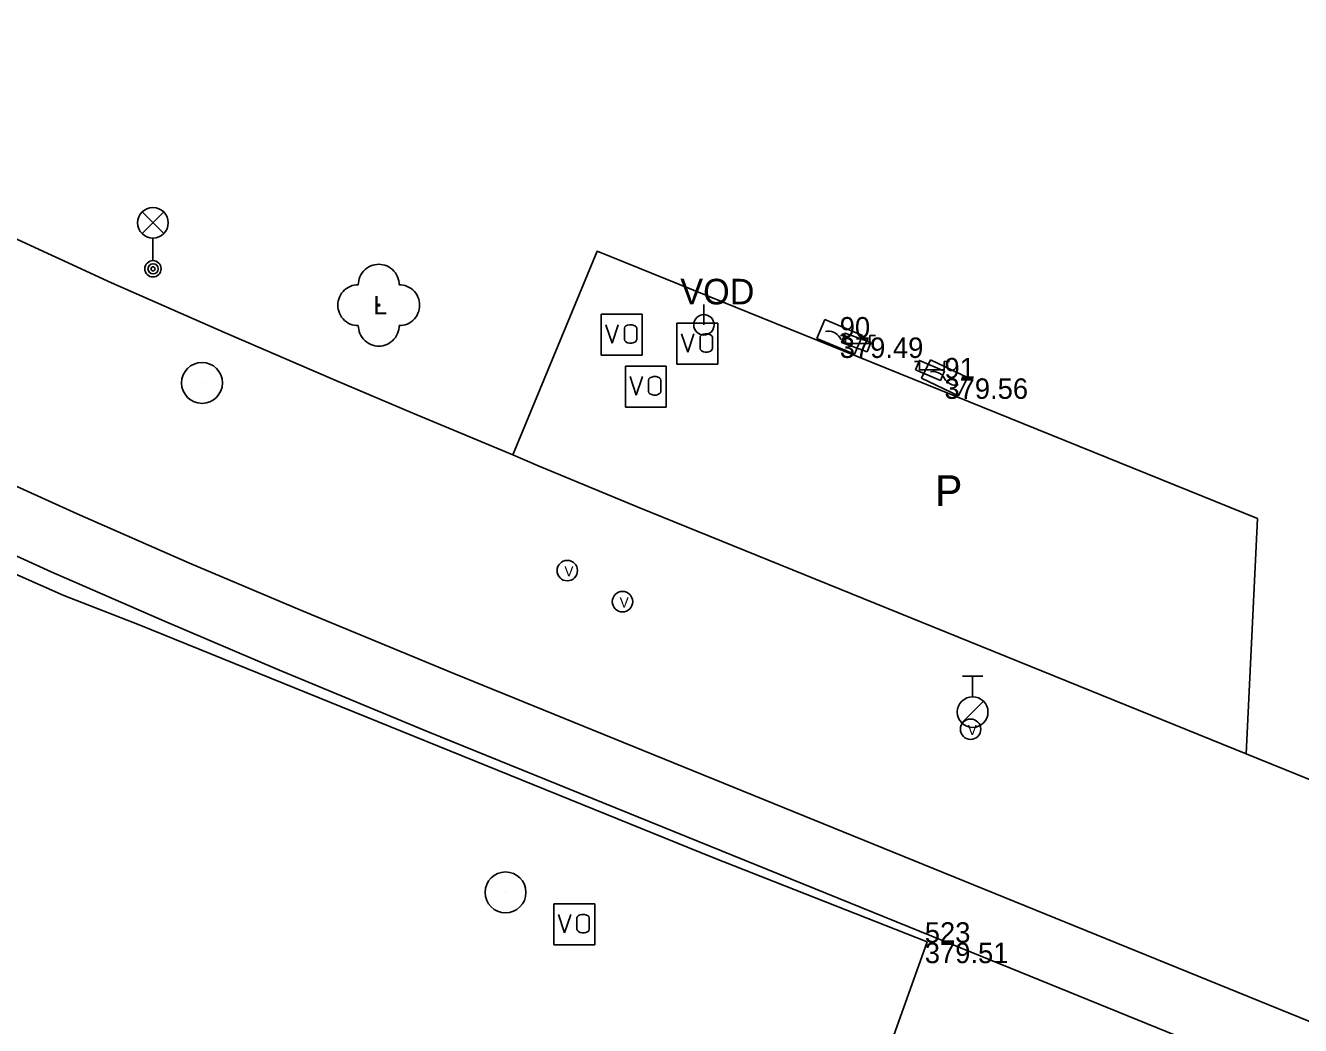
# Model space of a CAD drawing. Extents: x -836568 to -836015, y -1070547 to -1070212.
# Drawn here: x -836391.76 to -836360.58, y -1070409.55 to -1070385.1 of the extents above; entities that cross this region are included whole.
import ezdxf

# ---------------------------------------------------------------- set-up
doc = ezdxf.new("R2010")
doc.units = 0
for name, color, linetype in [('BodPole_mer', 7, 'Continuous'), ('BodPole_popis', 7, 'Continuous'), ('Doprava_hranice', 7, 'Continuous'), ('Doprava_kody', 7, 'Continuous'), ('PovrZnIS_body', 7, 'Continuous'), ('PovrZnIS_hranice', 7, 'Continuous'), ('PovrZnIS_kody', 7, 'Continuous'), ('Stavby_linie', 7, 'Continuous'), ('Zelen_body', 7, 'Continuous')]:
    doc.layers.add(name, color=color, linetype=linetype)

msp = doc.modelspace()

# ---------------------------------------------------------------- linework, layer by layer
at = {"layer": 'BodPole_mer'}
for p, q in [((-836377.78, -1070390.62), (-836377.78, -1070390.62)), ((-836388.64, -1070391.05), (-836388.64, -1070391.05)), ((-836389.65, -1070391.39), (-836389.65, -1070391.39)), ((-836383.12, -1070391.94), (-836383.12, -1070391.94)), ((-836375.17, -1070392.42), (-836375.17, -1070392.42)), ((-836386.89, -1070392.61), (-836386.89, -1070392.61)), ((-836377.18, -1070392.66), (-836377.18, -1070392.66)), ((-836375.33, -1070392.88), (-836375.33, -1070392.88)), ((-836371.85, -1070392.73), (-836371.85, -1070392.73)), ((-836371.81, -1070392.85), (-836371.81, -1070392.85)), ((-836371.81, -1070392.85), (-836371.81, -1070392.85)), ((-836371.72, -1070392.62), (-836371.72, -1070392.62)), ((-836371.72, -1070392.62), (-836371.72, -1070392.62)), ((-836371.09, -1070392.85), (-836371.09, -1070392.85)), ((-836371.09, -1070392.85), (-836371.09, -1070392.85)), ((-836371.18, -1070393.08), (-836371.18, -1070393.08)), ((-836371.18, -1070393.08), (-836371.18, -1070393.08)), ((-836370, -1070393.52), (-836370, -1070393.52)), ((-836370, -1070393.52), (-836370, -1070393.52)), ((-836369.9, -1070393.29), (-836369.9, -1070393.29)), ((-836369.9, -1070393.29), (-836369.9, -1070393.29)), ((-836384.17, -1070393.78), (-836384.17, -1070393.78)), ((-836369.39, -1070393.78), (-836369.39, -1070393.78)), ((-836369.39, -1070393.78), (-836369.39, -1070393.78)), ((-836369.29, -1070393.55), (-836369.29, -1070393.55)), ((-836369.29, -1070393.55), (-836369.29, -1070393.55)), ((-836369.29, -1070393.73), (-836369.29, -1070393.73)), ((-836387.44, -1070393.84), (-836387.44, -1070393.84)), ((-836376.59, -1070393.93), (-836376.59, -1070393.93)), ((-836382.29, -1070394.58), (-836382.29, -1070394.58)), ((-836379.84, -1070395.6), (-836379.84, -1070395.6)), ((-836379.24, -1070395.86), (-836379.24, -1070395.86)), ((-836376.76, -1070396.89), (-836376.76, -1070396.89)), ((-836390.49, -1070397.04), (-836390.49, -1070397.04)), ((-836361.64, -1070397.16), (-836361.64, -1070397.16)), ((-836391.13, -1070398.46), (-836391.13, -1070398.46)), ((-836387.75, -1070398.25), (-836387.75, -1070398.25)), ((-836378.51, -1070398.43), (-836378.51, -1070398.43)), ((-836390.82, -1070399.04), (-836390.82, -1070399.04)), ((-836385.01, -1070399.41), (-836385.01, -1070399.41)), ((-836377.16, -1070399.19), (-836377.16, -1070399.19)), ((-836388.98, -1070399.76), (-836388.98, -1070399.76)), ((-836388.36, -1070399.67), (-836388.36, -1070399.67)), ((-836369.55, -1070399.81), (-836369.55, -1070399.81)), ((-836385.59, -1070400.85), (-836385.59, -1070400.85)), ((-836381.28, -1070400.95), (-836381.28, -1070400.95)), ((-836368.6, -1070401.89), (-836368.6, -1070401.89)), ((-836381.91, -1070402.37), (-836381.91, -1070402.37)), ((-836368.65, -1070402.31), (-836368.65, -1070402.31)), ((-836361.91, -1070402.91), (-836361.91, -1070402.91)), ((-836374.95, -1070405.45), (-836374.95, -1070405.45)), ((-836369.06, -1070405.92), (-836369.06, -1070405.92)), ((-836380.02, -1070406.3), (-836380.02, -1070406.3)), ((-836378.34, -1070407.08), (-836378.34, -1070407.08)), ((-836369.77, -1070407.53), (-836369.77, -1070407.53)), ((-836369.71, -1070407.51), (-836369.71, -1070407.51)), ((-836369.6, -1070407.37), (-836369.6, -1070407.37))]:
    msp.add_line(p, q, dxfattribs=at)
at = {"layer": 'Doprava_hranice'}
for points in [[(-836354.29, -1070413.6), (-836369.6, -1070407.37), (-836381.91, -1070402.37), (-836385.59, -1070400.85), (-836388.36, -1070399.67), (-836391.13, -1070398.46), (-836393.85, -1070397.22), (-836395.73, -1070396.35), (-836398.41, -1070395.08), (-836401.16, -1070393.77), (-836403.85, -1070392.4), (-836406.54, -1070391.05), (-836409.24, -1070389.65), (-836411.89, -1070388.24), (-836414.55, -1070386.78), (-836417.54, -1070385.1), (-836418.59, -1070387.07)], [(-836396.93, -1070387.99), (-836395.12, -1070388.87), (-836392.38, -1070390.14), (-836389.65, -1070391.39), (-836386.89, -1070392.61), (-836384.17, -1070393.78), (-836382.29, -1070394.58), (-836379.84, -1070395.6), (-836379.24, -1070395.86), (-836376.76, -1070396.89), (-836369.55, -1070399.81), (-836361.91, -1070402.91), (-836351.68, -1070407.06)], [(-836379.84, -1070395.6), (-836377.78, -1070390.62), (-836361.64, -1070397.16), (-836361.91, -1070402.91)], [(-836294.78, -1070436.14), (-836298.75, -1070434.54), (-836300.99, -1070433.61), (-836301.95, -1070433.21), (-836302.68, -1070432.9), (-836308.94, -1070430.38), (-836313.57, -1070428.51), (-836318.21, -1070426.63), (-836324.7, -1070423.98), (-836329.32, -1070422.08), (-836333.96, -1070420.19), (-836342.84, -1070416.58), (-836353.67, -1070412.18), (-836369.06, -1070405.92), (-836381.28, -1070400.95), (-836385.01, -1070399.41), (-836387.75, -1070398.25), (-836390.49, -1070397.04), (-836393.21, -1070395.81), (-836395.03, -1070394.97), (-836397.75, -1070393.68), (-836399.24, -1070392.97)]]:
    msp.add_lwpolyline(points, dxfattribs=at)
at = {"layer": 'PovrZnIS_body'}
for p, q in [((-836388.905, -1070390.19), (-836388.375, -1070389.66)), ((-836388.905, -1070389.66), (-836388.375, -1070390.19)), ((-836388.64, -1070390.85), (-836388.64, -1070390.3)), ((-836375.17, -1070392.42), (-836375.17, -1070391.92)), ((-836376.68, -1070392.16), (-836377.68, -1070392.16)), ((-836377.68, -1070392.16), (-836377.68, -1070393.16)), ((-836376.68, -1070393.16), (-836376.68, -1070392.16)), ((-836374.83, -1070392.38), (-836375.83, -1070392.38)), ((-836375.83, -1070392.38), (-836375.83, -1070393.38)), ((-836374.83, -1070393.38), (-836374.83, -1070392.38)), ((-836372.408, -1070392.754), (-836372.214, -1070392.293)), ((-836372.214, -1070392.293), (-836371.292, -1070392.68)), ((-836371.486, -1070393.141), (-836372.408, -1070392.754)), ((-836371.292, -1070392.68), (-836371.486, -1070393.141)), ((-836377.68, -1070393.16), (-836376.68, -1070393.16)), ((-836376.09, -1070393.43), (-836377.09, -1070393.43)), ((-836377.09, -1070393.43), (-836377.09, -1070394.43)), ((-836376.09, -1070394.43), (-836376.09, -1070393.43)), ((-836375.83, -1070393.38), (-836374.83, -1070393.38)), ((-836369.848, -1070393.728), (-836369.633, -1070393.277)), ((-836369.633, -1070393.277), (-836368.73, -1070393.706)), ((-836368.945, -1070394.158), (-836369.848, -1070393.728)), ((-836368.73, -1070393.706), (-836368.945, -1070394.158)), ((-836377.09, -1070394.43), (-836376.09, -1070394.43)), ((-836368.85, -1070401.015), (-836368.35, -1070401.015)), ((-836368.6, -1070401.015), (-836368.6, -1070401.515)), ((-836368.335, -1070401.625), (-836368.865, -1070402.155)), ((-836377.84, -1070406.58), (-836378.84, -1070406.58)), ((-836378.84, -1070406.58), (-836378.84, -1070407.58)), ((-836377.84, -1070407.58), (-836377.84, -1070406.58)), ((-836378.84, -1070407.58), (-836377.84, -1070407.58))]:
    msp.add_line(p, q, dxfattribs=at)
for points in [[(-836377.565, -1070392.417), (-836377.415, -1070392.867)], [(-836377.415, -1070392.867), (-836377.265, -1070392.417)], [(-836377.113, -1070392.501), (-836377.103, -1070392.471), (-836377.08, -1070392.448), (-836377.034, -1070392.427), (-836376.989, -1070392.417), (-836376.929, -1070392.417), (-836376.9, -1070392.425), (-836376.843, -1070392.45), (-836376.823, -1070392.471), (-836376.813, -1070392.501)], [(-836377.113, -1070392.782), (-836377.113, -1070392.501)], [(-836376.813, -1070392.782), (-836376.813, -1070392.501)], [(-836372.197, -1070392.584), (-836372.15, -1070392.576), (-836372.1, -1070392.576), (-836372.049, -1070392.583), (-836371.999, -1070392.599), (-836371.953, -1070392.623), (-836371.912, -1070392.654), (-836371.878, -1070392.691), (-836371.85, -1070392.73)], [(-836377.113, -1070392.782), (-836377.103, -1070392.813), (-836377.08, -1070392.835), (-836377.034, -1070392.857), (-836376.989, -1070392.867), (-836376.929, -1070392.867), (-836376.9, -1070392.859), (-836376.843, -1070392.833), (-836376.823, -1070392.813), (-836376.813, -1070392.782)], [(-836375.715, -1070392.637), (-836375.565, -1070393.087)], [(-836375.565, -1070393.087), (-836375.415, -1070392.637)], [(-836375.263, -1070392.721), (-836375.253, -1070392.691), (-836375.23, -1070392.668), (-836375.184, -1070392.647), (-836375.139, -1070392.637), (-836375.079, -1070392.637), (-836375.05, -1070392.645), (-836374.993, -1070392.67), (-836374.973, -1070392.691), (-836374.963, -1070392.721)], [(-836375.263, -1070393.002), (-836375.263, -1070392.721)], [(-836374.963, -1070393.002), (-836374.963, -1070392.721)], [(-836371.85, -1070392.73), (-836371.823, -1070392.769), (-836371.788, -1070392.805), (-836371.747, -1070392.836), (-836371.701, -1070392.86), (-836371.652, -1070392.876), (-836371.601, -1070392.884), (-836371.551, -1070392.883), (-836371.504, -1070392.875)], [(-836375.263, -1070393.002), (-836375.253, -1070393.033), (-836375.23, -1070393.055), (-836375.184, -1070393.077), (-836375.139, -1070393.087), (-836375.079, -1070393.087), (-836375.05, -1070393.079), (-836374.993, -1070393.053), (-836374.973, -1070393.033), (-836374.963, -1070393.002)], [(-836376.975, -1070393.687), (-836376.825, -1070394.137)], [(-836376.825, -1070394.137), (-836376.675, -1070393.687)], [(-836376.523, -1070393.771), (-836376.513, -1070393.741), (-836376.49, -1070393.718), (-836376.444, -1070393.697), (-836376.399, -1070393.687), (-836376.339, -1070393.687), (-836376.31, -1070393.695), (-836376.253, -1070393.72), (-836376.233, -1070393.741), (-836376.223, -1070393.771)], [(-836376.523, -1070394.052), (-836376.523, -1070393.771)], [(-836376.223, -1070394.052), (-836376.223, -1070393.771)], [(-836369.63, -1070393.568), (-836369.582, -1070393.562), (-836369.532, -1070393.564), (-836369.482, -1070393.574), (-836369.433, -1070393.593), (-836369.388, -1070393.619), (-836369.349, -1070393.652), (-836369.316, -1070393.689), (-836369.29, -1070393.73)], [(-836369.29, -1070393.73), (-836369.265, -1070393.771), (-836369.232, -1070393.808), (-836369.192, -1070393.841), (-836369.148, -1070393.867), (-836369.099, -1070393.885), (-836369.049, -1070393.895), (-836368.999, -1070393.897), (-836368.951, -1070393.891)], [(-836376.523, -1070394.052), (-836376.513, -1070394.083), (-836376.49, -1070394.105), (-836376.444, -1070394.127), (-836376.399, -1070394.137), (-836376.339, -1070394.137), (-836376.31, -1070394.129), (-836376.253, -1070394.103), (-836376.233, -1070394.083), (-836376.223, -1070394.052)], [(-836378.725, -1070406.837), (-836378.575, -1070407.287)], [(-836378.575, -1070407.287), (-836378.425, -1070406.837)], [(-836378.273, -1070406.921), (-836378.263, -1070406.891), (-836378.24, -1070406.868), (-836378.194, -1070406.847), (-836378.149, -1070406.837), (-836378.089, -1070406.837), (-836378.06, -1070406.845), (-836378.003, -1070406.87), (-836377.983, -1070406.891), (-836377.973, -1070406.921)], [(-836378.273, -1070407.202), (-836378.273, -1070406.921)], [(-836377.973, -1070407.202), (-836377.973, -1070406.921)], [(-836378.273, -1070407.202), (-836378.263, -1070407.233), (-836378.24, -1070407.255), (-836378.194, -1070407.277), (-836378.149, -1070407.287), (-836378.089, -1070407.287), (-836378.06, -1070407.279), (-836378.003, -1070407.253), (-836377.983, -1070407.233), (-836377.973, -1070407.202)]]:
    msp.add_lwpolyline(points, dxfattribs=at)
for centre, radius in [((-836375.17, -1070392.42), 0.25), ((-836387.44, -1070393.84), 0.5), ((-836378.51, -1070398.43), 0.25), ((-836377.16, -1070399.19), 0.25), ((-836368.6, -1070401.89), 0.375), ((-836368.65, -1070402.31), 0.25), ((-836380.02, -1070406.3), 0.5)]:
    msp.add_circle(centre, radius, dxfattribs=at)
for centre, major_axis in [((-836388.64, -1070389.925), (0.375, 0)), ((-836388.64, -1070391.05), (0.2, 0)), ((-836388.636, -1070391.05), (0.125, 0)), ((-836388.636, -1070391.05), (0.05, 0))]:
    msp.add_ellipse(centre, major_axis=major_axis, ratio=0.999998, dxfattribs=at)
at = {"layer": 'PovrZnIS_hranice'}
for p, q in [((-836371.81, -1070392.85), (-836371.18, -1070393.08)), ((-836371.81, -1070392.85), (-836371.18, -1070393.08)), ((-836370, -1070393.52), (-836369.39, -1070393.78)), ((-836370, -1070393.52), (-836369.39, -1070393.78))]:
    msp.add_line(p, q, dxfattribs=at)
for points in [[(-836371.81, -1070392.85), (-836371.72, -1070392.62), (-836371.09, -1070392.85), (-836371.18, -1070393.08)], [(-836371.81, -1070392.85), (-836371.72, -1070392.62), (-836371.09, -1070392.85), (-836371.18, -1070393.08)], [(-836370, -1070393.52), (-836369.9, -1070393.29), (-836369.29, -1070393.55), (-836369.39, -1070393.78)], [(-836370, -1070393.52), (-836369.9, -1070393.29), (-836369.29, -1070393.55), (-836369.39, -1070393.78)]]:
    msp.add_lwpolyline(points, dxfattribs=at)
at = {"layer": 'PovrZnIS_kody'}
for p, q in [((-836371.831, -1070392.68), (-836371.71, -1070392.68)), ((-836371.831, -1070392.68), (-836371.71, -1070392.68)), ((-836371.71, -1070392.68), (-836371.71, -1070392.88)), ((-836371.71, -1070392.68), (-836371.71, -1070392.88)), ((-836371.71, -1070392.88), (-836371.11, -1070392.88)), ((-836371.71, -1070392.88), (-836371.11, -1070392.88)), ((-836371.11, -1070392.88), (-836371.11, -1070392.68)), ((-836371.11, -1070392.68), (-836370.976, -1070392.68)), ((-836371.11, -1070392.88), (-836371.11, -1070392.68)), ((-836371.11, -1070392.68), (-836370.976, -1070392.68)), ((-836370.021, -1070393.32), (-836369.9, -1070393.32)), ((-836370.021, -1070393.32), (-836369.9, -1070393.32)), ((-836369.9, -1070393.32), (-836369.9, -1070393.52)), ((-836369.9, -1070393.32), (-836369.9, -1070393.52)), ((-836369.9, -1070393.52), (-836369.3, -1070393.52)), ((-836369.9, -1070393.52), (-836369.3, -1070393.52)), ((-836369.3, -1070393.52), (-836369.3, -1070393.32)), ((-836369.3, -1070393.32), (-836369.166, -1070393.32)), ((-836369.3, -1070393.52), (-836369.3, -1070393.32)), ((-836369.3, -1070393.32), (-836369.166, -1070393.32))]:
    msp.add_line(p, q, dxfattribs=at)
at = {"layer": 'Stavby_linie'}
msp.add_line((-836393.4, -1070397.9), (-836390.82, -1070399.04), dxfattribs=at)
for points in [[(-836369.71, -1070407.51), (-836374.95, -1070405.45), (-836388.98, -1070399.76), (-836390.82, -1070399.04)], [(-836407.72, -1070434.26), (-836402.65, -1070436.98), (-836392.21, -1070442.72), (-836384.11, -1070447.06), (-836383.25, -1070443.91), (-836379.69, -1070432.5), (-836376.35, -1070424), (-836370.7, -1070410.27), (-836369.71, -1070407.51)]]:
    msp.add_lwpolyline(points, dxfattribs=at)
at = {"layer": 'Zelen_body'}
msp.add_line((-836383.12, -1070391.94), (-836383.12, -1070391.94), dxfattribs=at)
for points in [[(-836383.62, -1070391.44), (-836383.618, -1070391.392), (-836383.61, -1070391.343), (-836383.598, -1070391.293), (-836383.58, -1070391.244), (-836383.556, -1070391.195), (-836383.527, -1070391.149), (-836383.493, -1070391.106), (-836383.454, -1070391.067), (-836383.411, -1070391.033), (-836383.365, -1070391.004), (-836383.316, -1070390.98), (-836383.267, -1070390.962), (-836383.217, -1070390.95), (-836383.168, -1070390.942), (-836383.12, -1070390.94), (-836383.072, -1070390.942), (-836383.023, -1070390.95), (-836382.973, -1070390.962), (-836382.924, -1070390.98), (-836382.875, -1070391.004), (-836382.829, -1070391.033), (-836382.786, -1070391.067), (-836382.747, -1070391.106), (-836382.713, -1070391.149), (-836382.684, -1070391.195), (-836382.66, -1070391.244), (-836382.642, -1070391.293), (-836382.63, -1070391.343), (-836382.622, -1070391.392), (-836382.62, -1070391.44)], [(-836383.62, -1070392.44), (-836383.668, -1070392.438), (-836383.717, -1070392.43), (-836383.767, -1070392.418), (-836383.816, -1070392.4), (-836383.865, -1070392.376), (-836383.911, -1070392.347), (-836383.954, -1070392.313), (-836383.993, -1070392.274), (-836384.027, -1070392.231), (-836384.056, -1070392.185), (-836384.08, -1070392.136), (-836384.098, -1070392.087), (-836384.11, -1070392.037), (-836384.118, -1070391.988), (-836384.12, -1070391.94), (-836384.118, -1070391.892), (-836384.11, -1070391.843), (-836384.098, -1070391.793), (-836384.08, -1070391.744), (-836384.056, -1070391.695), (-836384.027, -1070391.649), (-836383.993, -1070391.606), (-836383.954, -1070391.567), (-836383.911, -1070391.533), (-836383.865, -1070391.504), (-836383.816, -1070391.48), (-836383.767, -1070391.462), (-836383.717, -1070391.45), (-836383.668, -1070391.442), (-836383.62, -1070391.44)], [(-836382.62, -1070391.44), (-836382.572, -1070391.442), (-836382.523, -1070391.45), (-836382.473, -1070391.462), (-836382.424, -1070391.48), (-836382.375, -1070391.504), (-836382.329, -1070391.533), (-836382.286, -1070391.567), (-836382.247, -1070391.606), (-836382.213, -1070391.649), (-836382.184, -1070391.695), (-836382.16, -1070391.744), (-836382.142, -1070391.793), (-836382.13, -1070391.843), (-836382.122, -1070391.892), (-836382.12, -1070391.94), (-836382.122, -1070391.988), (-836382.13, -1070392.037), (-836382.142, -1070392.087), (-836382.16, -1070392.136), (-836382.184, -1070392.185), (-836382.213, -1070392.231), (-836382.247, -1070392.274), (-836382.286, -1070392.313), (-836382.329, -1070392.347), (-836382.375, -1070392.376), (-836382.424, -1070392.4), (-836382.473, -1070392.418), (-836382.523, -1070392.43), (-836382.572, -1070392.438), (-836382.62, -1070392.44)], [(-836382.62, -1070392.44), (-836382.622, -1070392.488), (-836382.63, -1070392.537), (-836382.642, -1070392.587), (-836382.66, -1070392.636), (-836382.684, -1070392.685), (-836382.713, -1070392.731), (-836382.747, -1070392.774), (-836382.786, -1070392.813), (-836382.829, -1070392.847), (-836382.875, -1070392.876), (-836382.924, -1070392.9), (-836382.973, -1070392.918), (-836383.023, -1070392.93), (-836383.072, -1070392.938), (-836383.12, -1070392.94), (-836383.168, -1070392.938), (-836383.217, -1070392.93), (-836383.267, -1070392.918), (-836383.316, -1070392.9), (-836383.365, -1070392.876), (-836383.411, -1070392.847), (-836383.454, -1070392.813), (-836383.493, -1070392.774), (-836383.527, -1070392.731), (-836383.556, -1070392.685), (-836383.58, -1070392.636), (-836383.598, -1070392.587), (-836383.61, -1070392.537), (-836383.618, -1070392.488), (-836383.62, -1070392.44)]]:
    msp.add_lwpolyline(points, dxfattribs=at)
msp.add_ellipse((-836383.12, -1070391.94), major_axis=(0.025, 0), ratio=0.999997, dxfattribs=at)

# ---------------------------------------------------------------- texts
at = {"layer": 'BodPole_popis'}
for s, p in [('90', (-836371.85, -1070392.73)), ('379.49', (-836371.85, -1070393.23)), ('91', (-836369.29, -1070393.73)), ('379.56', (-836369.29, -1070394.23)), ('523', (-836369.77, -1070407.53)), ('379.51', (-836369.77, -1070408.03))]:
    msp.add_text(s, height=0.5, dxfattribs=at).set_placement(p)
at = {"layer": 'Doprava_kody'}
msp.add_text('P', height=0.75, dxfattribs=at).set_placement((-836369.52, -1070396.85))
at = {"layer": 'PovrZnIS_body'}
for s, height, p in [('VOD', 0.625, (-836375.747, -1070391.92)), ('V', 0.25, (-836378.581, -1070398.573)), ('V', 0.25, (-836377.231, -1070399.333)), ('V', 0.25, (-836368.721, -1070402.453))]:
    msp.add_text(s, height=height, dxfattribs=at).set_placement(p)
at = {"layer": 'Zelen_body'}
msp.add_text('L', height=0.45, dxfattribs=at).set_placement((-836383.251, -1070392.165))

doc.saveas('drawing.dxf')
